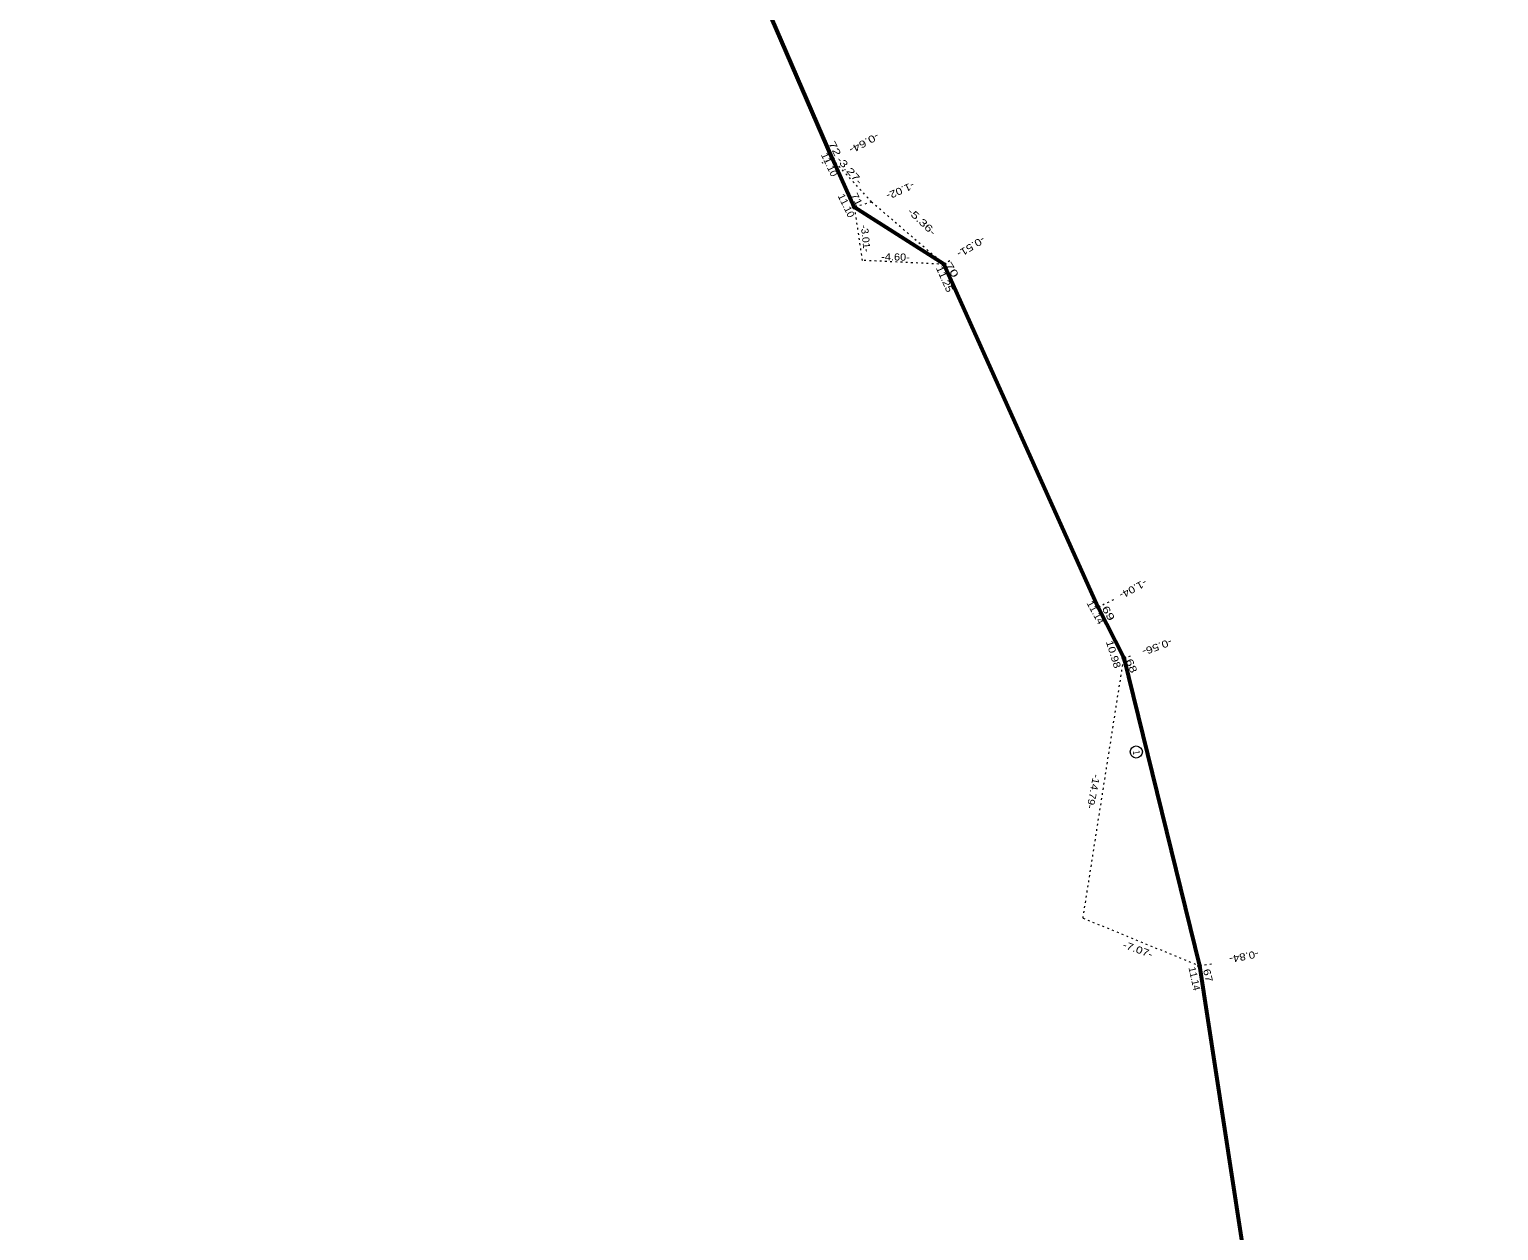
# Model space of a CAD drawing. Extents: x -603113 to -602961, y -1157278 to -1156712.
# Drawn here: x -603059.4 to -602976.9, y -1156917.2 to -1156849.8 of the extents above; entities that cross this region are included whole.
import ezdxf
from ezdxf.enums import TextEntityAlignment as Align

# ---------------------------------------------------------------- set-up
doc = ezdxf.new("R2010")
doc.units = 0
doc.header["$LTSCALE"] = 0.16
doc.header["$PDMODE"] = 32
doc.header["$PDSIZE"] = 0.08
doc.linetypes.add('DOTTED', pattern=[1.5, 0.3, -1.2])
for name, color, linetype, lineweight in [('12', 7, 'Continuous', 53), ('14', 7, 'DOTTED', 13), ('15', 7, 'Continuous', 13)]:
    doc.layers.add(name, color=color, linetype=linetype, lineweight=lineweight)
doc.layers.add('35', color=7, linetype='Continuous')

msp = doc.modelspace()

# ---------------------------------------------------------------- linework, layer by layer
at = {"layer": '12'}
for points in [[(-603008.05, -1156862.95), (-603013.08, -1156859.75), (-603014.31, -1156857.03), (-603020.32, -1156843.12), (-603025.746, -1156832.154), (-603033.325, -1156818.288), (-603040.317, -1156805.906), (-603047.333, -1156795.776), (-603054.033, -1156784.062), (-603059.389, -1156775.282)], [(-603008.05, -1156862.95), (-602999.4, -1156882.19), (-602997.95, -1156885.06), (-602993.7, -1156902.35), (-602990.97, -1156920.18), (-602988.99, -1156937.68), (-602986.98, -1156953.32), (-602985.31, -1156968.13), (-602985.33, -1156971.03), (-602984.5, -1156980.36), (-602982.87, -1156994.49), (-602980.87, -1157012.29), (-602979.02, -1157028.94), (-602976.91, -1157038.635)]]:
    msp.add_lwpolyline(points, dxfattribs=at)
at = {"layer": '14'}
for p, q in [((-603014.31, -1156857.03), (-603014.898, -1156857.274)), ((-603012.11, -1156859.45), (-603014.31, -1156857.03)), ((-603013.08, -1156859.75), (-603012.64, -1156862.73)), ((-603008.05, -1156862.95), (-603012.64, -1156862.73)), ((-603008.05, -1156862.95), (-603007.62, -1156862.67)), ((-602999.4, -1156882.19), (-602998.452, -1156881.751)), ((-603000.24, -1156899.67), (-602997.95, -1156885.06)), ((-602997.95, -1156885.06), (-602997.418, -1156884.893)), ((-603000.24, -1156899.67), (-602993.7, -1156902.35)), ((-602993.7, -1156902.35), (-602992.868, -1156902.204))]:
    msp.add_line(p, q, dxfattribs=at)
msp.add_lwpolyline([(-603008.05, -1156862.95), (-603012.11, -1156859.45), (-603013.08, -1156859.75)], dxfattribs=at)
at = {"layer": '15'}
for centre, radius in [((-603014.31, -1156857.03), 0.1), ((-603013.08, -1156859.75), 0.1), ((-603008.05, -1156862.95), 0.1), ((-602999.4, -1156882.19), 0.1), ((-602997.95, -1156885.06), 0.1), ((-602997.2499, -1156890.3394), 0.3414), ((-602993.7, -1156902.35), 0.1)]:
    msp.add_circle(centre, radius, dxfattribs=at)
for p in [(-603014.31, -1156857.03), (-603013.08, -1156859.75), (-603008.05, -1156862.95), (-602999.4, -1156882.19), (-602997.95, -1156885.06), (-602993.7, -1156902.35)]:
    msp.add_point(p, dxfattribs=at)

# ---------------------------------------------------------------- texts
at = {"layer": '14'}
for s, rotation, width, p in [('-0.64-', 208.739, 1.3, (-603011.827, -1156855.537)), ('-3.27-', 311.024, 1.35, (-603014.111, -1156857.094)), ('-1.02-', 203.757, 1.2, (-603009.804, -1156858.297)), ('-5.36-', 316.385, 1.4, (-603010.131, -1156860.02)), ('-3.01-', 275.947, 1.1, (-603012.716, -1156860.75)), ('-0.51-', 211.815, 1.25, (-603005.891, -1156861.344)), ('-4.60-', 358.989, 1.15, (-603011.573, -1156862.722)), ('-1.04-', 208.6, 1.2, (-602996.789, -1156880.614)), ('-0.56-', 200.513, 1.25, (-602995.331, -1156883.947)), ('-14.79-', 258.833, 1.15, (-602999.661, -1156891.567)), ('-7.07-', 340.08, 1.25, (-602998.054, -1156901.322)), ('-0.84-', 191.115, 1.2, (-602990.416, -1156901.475))]:
    msp.add_text(s, height=0.4, rotation=rotation, dxfattribs=dict(at, width=width)).set_placement(p)
at = {"layer": '15'}
for s, rotation, width, p in [('72', 296.77, 1.45, (-603014.549, -1156856.156)), ('71', 296.963, 1.2, (-603013.288, -1156859.063)), ('70', 301.845, 1.5, (-603008.006, -1156862.984)), ('69', 298.904, 1.45, (-602999.199, -1156882.265)), ('68', 292.806, 1.35, (-602997.857, -1156885.208)), ('1', 279.483, 0.65, (-602997.451, -1156890.287)), ('67', 284.212, 1.25, (-602993.509, -1156902.578))]:
    msp.add_text(s, height=0.4, rotation=rotation, dxfattribs=dict(at, width=width)).set_placement(p)
at = {"layer": '35'}
for s, rotation, width, p in [('11.10', 295.278, 1.05, (-603014.6608, -1156857.4361)), ('11.10', 296.122, 1.05, (-603013.7107, -1156859.7429)), ('11.25', 294.17, 1.15, (-603008.1906, -1156863.8621)), ('11.14', 298.91, 1.05, (-602999.7129, -1156882.5968)), ('10.98', 287.367, 1.2, (-602998.7192, -1156884.9163))]:
    msp.add_text(s, height=0.4, rotation=rotation, dxfattribs=dict(at, width=width)).set_placement(p, align=Align.CENTER)
msp.add_text('11.14', height=0.4, rotation=282.282, dxfattribs=at).set_placement((-602994.1768, -1156903.113), align=Align.CENTER)

doc.saveas('drawing.dxf')
